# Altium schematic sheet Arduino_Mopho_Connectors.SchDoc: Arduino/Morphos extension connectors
size A4; Author: Ph.A; SheetNumber: 5; SheetTotal: 8
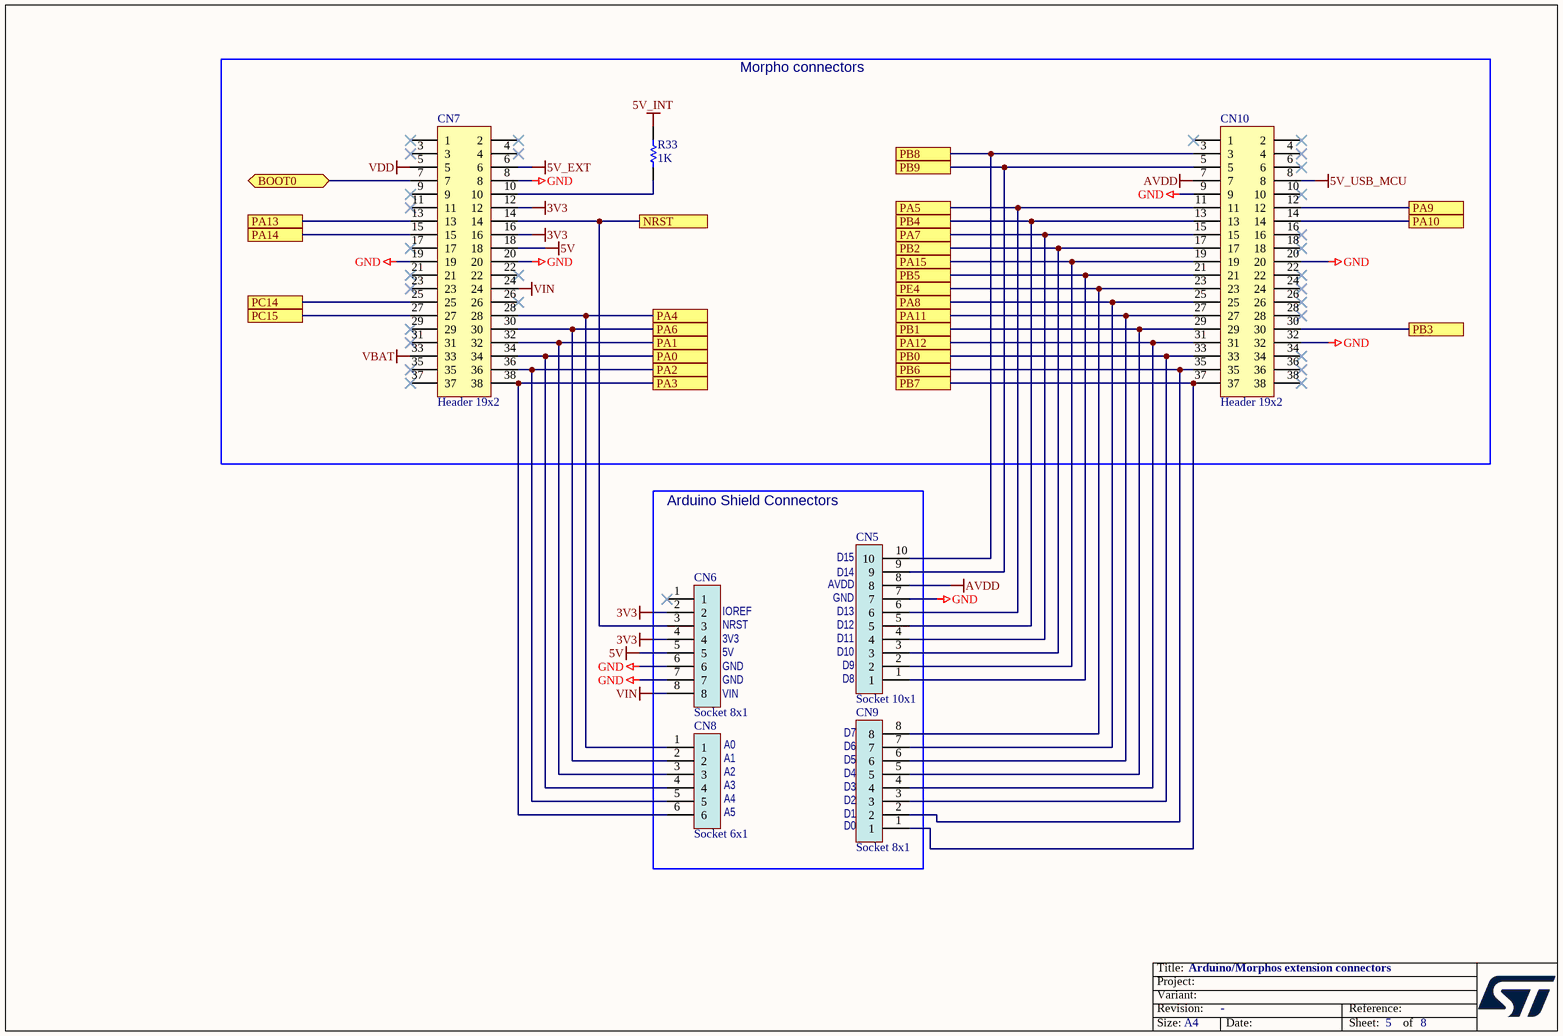
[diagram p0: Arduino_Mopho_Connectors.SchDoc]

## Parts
CN5  Socket 10x1  [CON_SAMTEC_SSW-110-01-X-S]
CN6  Socket 8x1  [CON_SAMTEC_SSW-108-01-X-S]
CN7  Header 19x2  [CON_SAMTEC_TSW-119-09-X-D]
CN8  Socket 6x1  [CON_SAMTEC_SSW-106-01-X-S]
CN9  Socket 8x1  [CON_SAMTEC_SSW-108-01-X-S]
CN10  Header 19x2  [CON_SAMTEC_TSW-119-09-X-D]
R33  value 1K  [R0402]  (hidden comment: Resistor)

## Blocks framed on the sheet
Morpho connectors: CN7 CN10 R33
Arduino Shield Connectors: CN5 CN6 CN8 CN9

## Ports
BOOT0 (bidir), NRST, PA0, PA1, PA2, PA3, PA4, PA5, PA6, PA7, PA8, PA9, PA10, PA11, PA12, PA13, PA14, PA15, PB0, PB1, PB2, PB3, PB4, PB5, PB6, PB7, PB8, PB9, PC14, PC15, PE4

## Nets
3V3: CN6.2 CN6.4 CN7.12 CN7.16
5V: CN6.5 CN7.18
5V_EXT: CN7.6
5V_INT: R33.2
5V_USB_MCU: CN10.8
AVDD: CN5.8 CN10.7
GND: CN5.7 CN6.6 CN6.7 CN7.8 CN7.19 CN7.20 CN10.9 CN10.20 CN10.32
VBAT: CN7.33
VDD: CN7.5
VIN: CN6.8 CN7.24
BOOT0: CN7.7 ; port BOOT0
NRST: CN6.3 CN7.14 ; port NRST
PA0: CN7.34 CN8.4 ; port PA0
PA1: CN7.32 CN8.3 ; port PA1
PA2: CN7.36 CN8.5 ; port PA2
PA3: CN7.38 CN8.6 ; port PA3
PA4: CN7.28 CN8.1 ; port PA4
PA5: CN5.6 CN10.11 ; port PA5
PA6: CN7.30 CN8.2 ; port PA6
PA7: CN5.4 CN10.15 ; port PA7
PA8: CN9.7 CN10.25 ; port PA8
PA9: CN10.12 ; port PA9
PA10: CN10.14 ; port PA10
PA11: CN9.6 CN10.27 ; port PA11
PA12: CN9.4 CN10.31 ; port PA12
PA13: CN7.13 ; port PA13
PA14: CN7.15 ; port PA14
PA15: CN5.2 CN10.19 ; port PA15
PB0: CN9.3 CN10.33 ; port PB0
PB1: CN9.5 CN10.29 ; port PB1
PB2: CN5.3 CN10.17 ; port PB2
PB3: CN10.30 ; port PB3
PB4: CN5.5 CN10.13 ; port PB4
PB5: CN5.1 CN10.21 ; port PB5
PB6: CN9.2 CN10.35 ; port PB6
PB7: CN9.1 CN10.37 ; port PB7
PB8: CN5.10 CN10.3 ; port PB8
PB9: CN5.9 CN10.5 ; port PB9
PC14: CN7.25 ; port PC14
PC15: CN7.27 ; port PC15
PE4: CN9.8 CN10.23 ; port PE4
NetCN7_10: CN7.10 R33.1

Not connected (* = marked no-connect by the designer): CN6 1*; CN7 1* 2* 3* 4* 9* 11* 17* 21* 22* 23* 26* 29* 31* 35* 37*; CN10 1* 2* 4* 6* 10* 16* 18* 22* 24* 26* 28* 34* 36* 38*

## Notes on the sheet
- (near CN5) D14
- (near CN5) D15
- (near CN6) 3V3
- (near CN6) NRST
- (near CN6) IOREF
- (near CN5) AVDD
- (near CN5) GND
- (near CN5) D10
- (near CN5) D11
- (near CN5) D12
- (near CN5) D13
- (near CN6) GND
- (near CN6) VIN
- (near CN6) 5V
- (near CN5) D9
- (near CN5) D8
- (near CN8) A0
- (near CN8) A1
- (near CN8) A2
- (near CN8) A3
- (near CN9) D3
- (near CN9) D4
- (near CN9) D5
- (near CN9) D6
- (near CN9) D7
- (near CN8) A5
- (near CN8) A4
- (near CN9) D0
- (near CN9) D1
- (near CN9) D2

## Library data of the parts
CN5 = MCD-02080: Socket 10x1, 2.54mm, VR, TH, height 8.51/2.64mm; Part_Type: Connector; Manufacturer_Part_Number: SSW-110-01-G-S; Manufacturer: SAMTEC; Alternate_Manufacturer_Part_Number: 218110S16198; Alternate_Manufacturer: JIUBABA; Part_Preference: Recommended; Order_Code_RS: 765-5736
CN6 CN9 = MCD-01743: Socket 8x1, 2.54mm, VR, TH, height 8.51/2.64mm; Part_Type: Connector; Manufacturer_Part_Number: SSW-108-01-G-S; Manufacturer: SAMTEC; Alternate_Manufacturer_Part_Number: 988.08.18.2.00050 (218108S16198); Alternate_Manufacturer: Jiubaba; Part_Preference: Recommended
CN7 CN10 = MCD-00213: Header, 19x2, 2,54mm, VR, TH, Height 5.84mm/10.16mm; Part_Type: Connector; Manufacturer_Part_Number: TSW-119-09-G-D; Manufacturer: SAMTEC; Part_Preference: Recommended
CN8 = MCD-02079: Socket 6x1, 2.54mm, VR, TH, height 8.51/2.64mm; Part_Type: Connector; Manufacturer_Part_Number: SSW-106-01-G-S; Manufacturer: SAMTEC; Alternate_Manufacturer_Part_Number: 218106S16198; Alternate_Manufacturer: JIUBABA; Part_Preference: Recommended; Order_Code_RS: 765-5666
R33 = MCD-00061: Resistor,1K,0402,1%,1/16W; Manufacturer_Part_Number: RC0402FR-071KL; Manufacturer: YAGEO; Part_Preference: Recommended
